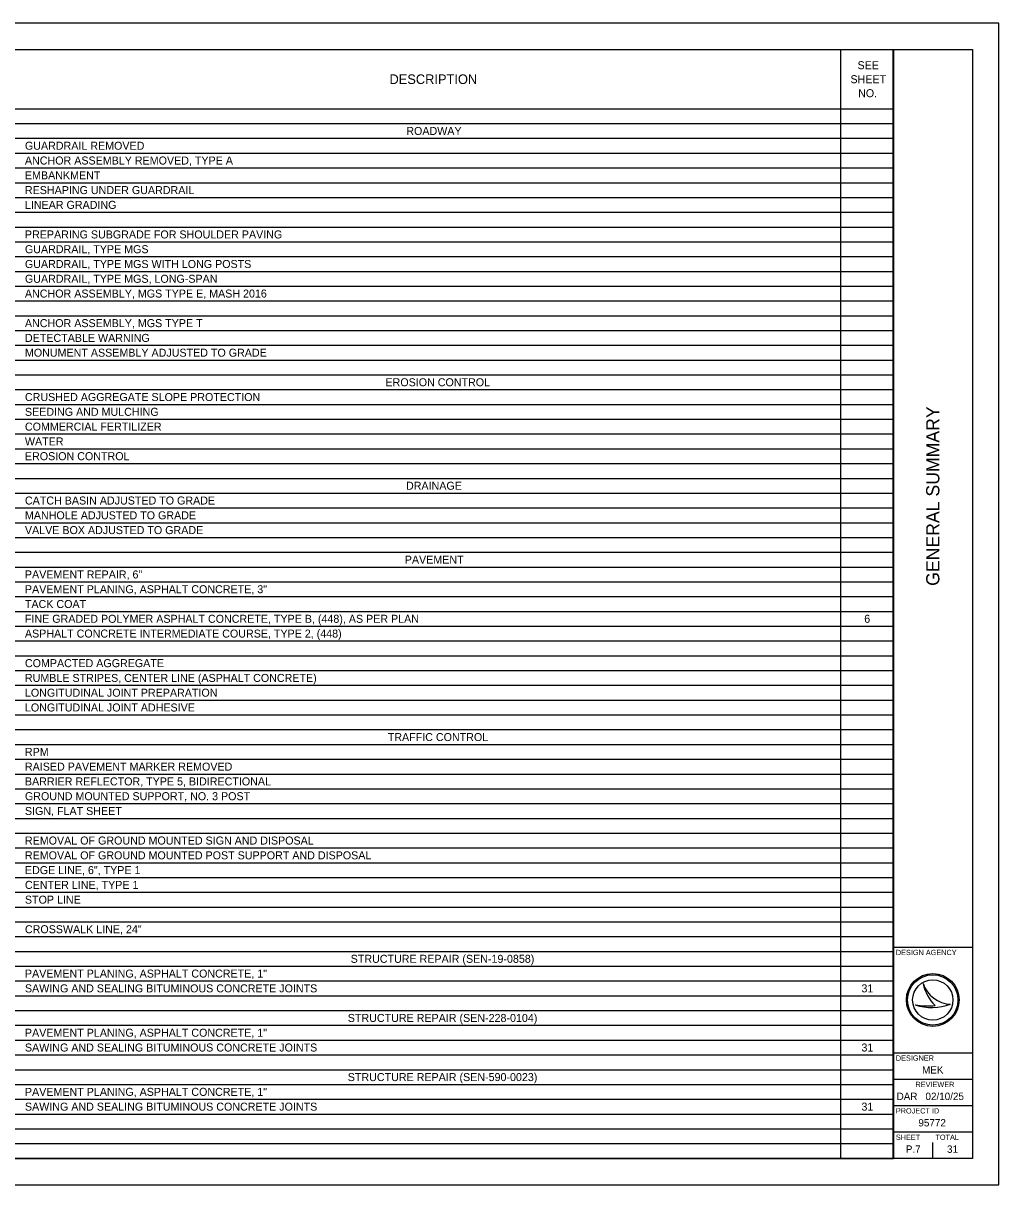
# Model space of a CAD drawing. Extents: x 0 to 34, y 0 to 22.
# Drawn here: x 15.52 to 34, y 0 to 22 of the extents above; entities that cross this region are included whole.
import ezdxf

# ---------------------------------------------------------------- set-up
doc = ezdxf.new("R2010")
doc.units = 0
for name, color, linetype in [('Default', 7, 'Continuous'), ('SH_Border', 7, 'Continuous'), ('SH_Cut_Line', 7, 'Continuous'), ('SH_Data', 7, 'Continuous')]:
    doc.layers.add(name, color=color, linetype=linetype)

msp = doc.modelspace()

# ---------------------------------------------------------------- linework, layer by layer
at = {"layer": 'Default'}
for p, q in [((1.5, 21.5), (32.004, 21.5)), ((30.999, 21.5), (30.999, 0.5)), ((32.004, 21.5), (32.004, 0.5)), ((1.5, 20.38), (32.004, 20.38)), ((1.5, 20.1), (32.004, 20.1)), ((1.5, 19.82), (32.004, 19.82)), ((1.5, 19.54), (32.004, 19.54)), ((1.5, 19.26), (32.004, 19.26)), ((1.5, 18.98), (32.004, 18.98)), ((1.5, 18.7), (32.004, 18.7)), ((1.5, 18.42), (32.004, 18.42)), ((1.5, 18.14), (32.004, 18.14)), ((1.5, 17.86), (32.004, 17.86)), ((1.5, 17.58), (32.004, 17.58)), ((1.5, 17.3), (32.004, 17.3)), ((1.5, 17.02), (32.004, 17.02)), ((1.5, 16.74), (32.004, 16.74)), ((1.5, 16.46), (32.004, 16.46)), ((1.5, 16.18), (32.004, 16.18)), ((1.5, 15.9), (32.004, 15.9)), ((1.5, 15.62), (32.004, 15.62)), ((1.5, 15.34), (32.004, 15.34)), ((1.5, 15.06), (32.004, 15.06)), ((1.5, 14.78), (32.004, 14.78)), ((1.5, 14.5), (32.004, 14.5)), ((1.5, 14.22), (32.004, 14.22)), ((1.5, 13.94), (32.004, 13.94)), ((1.5, 13.66), (32.004, 13.66)), ((1.5, 13.38), (32.004, 13.38)), ((1.5, 13.1), (32.004, 13.1)), ((1.5, 12.82), (32.004, 12.82)), ((1.5, 12.54), (32.004, 12.54)), ((1.5, 12.26), (32.004, 12.26)), ((1.5, 11.98), (32.004, 11.98)), ((1.5, 11.7), (32.004, 11.7)), ((1.5, 11.42), (32.004, 11.42)), ((1.5, 11.14), (32.004, 11.14)), ((1.5, 10.86), (32.004, 10.86)), ((1.5, 10.58), (32.004, 10.58)), ((1.5, 10.3), (32.004, 10.3)), ((1.5, 10.02), (32.004, 10.02)), ((1.5, 9.74), (32.004, 9.74)), ((1.5, 9.46), (32.004, 9.46)), ((1.5, 9.18), (32.004, 9.18)), ((1.5, 8.9), (32.004, 8.9)), ((1.5, 8.62), (32.004, 8.62)), ((1.5, 8.34), (32.004, 8.34)), ((1.5, 8.06), (32.004, 8.06)), ((1.5, 7.78), (32.004, 7.78)), ((1.5, 7.5), (32.004, 7.5)), ((1.5, 7.22), (32.004, 7.22)), ((1.5, 6.94), (32.004, 6.94)), ((1.5, 6.66), (32.004, 6.66)), ((1.5, 6.38), (32.004, 6.38)), ((1.5, 6.1), (32.004, 6.1)), ((1.5, 5.82), (32.004, 5.82)), ((1.5, 5.54), (32.004, 5.54)), ((1.5, 5.26), (32.004, 5.26)), ((1.5, 4.98), (32.004, 4.98)), ((1.5, 4.7), (32.004, 4.7)), ((1.5, 4.42), (32.004, 4.42)), ((1.5, 4.14), (32.004, 4.14)), ((1.5, 3.86), (32.004, 3.86)), ((1.5, 3.58), (32.004, 3.58)), ((1.5, 3.3), (32.004, 3.3)), ((1.5, 3.02), (32.004, 3.02)), ((1.5, 2.74), (32.004, 2.74)), ((1.5, 2.46), (32.004, 2.46)), ((1.5, 2.18), (32.004, 2.18)), ((1.5, 1.9), (32.004, 1.9)), ((1.5, 1.62), (32.004, 1.62)), ((1.5, 1.34), (32.004, 1.34)), ((1.5, 1.06), (32.004, 1.06)), ((1.5, 0.78), (32.004, 0.78)), ((1.5, 0.5), (32.004, 0.5))]:
    msp.add_line(p, q, dxfattribs=at)
at = {"layer": 'SH_Border'}
for p, q in [((32, 0.5), (32, 21.5)), ((32, 4.5), (33.5, 4.5)), ((32, 2.5), (33.5, 2.5)), ((32, 2), (33.5, 2)), ((32, 1.5), (33.5, 1.5)), ((32, 1), (33.5, 1))]:
    msp.add_line(p, q, dxfattribs=at)
msp.add_lwpolyline([(1.5, 21.5), (33.5, 21.5), (33.5, 0.5), (1.5, 0.5)], close=True, dxfattribs=at)
at = {"layer": 'SH_Cut_Line'}
msp.add_lwpolyline([(0, 0), (34, 0), (34, 22), (0, 22)], close=True, dxfattribs=at)
at = {"layer": 'SH_Data'}
for p, q in [((32.567, 3.81), (32.567, 3.81)), ((32.417, 3.41), (32.417, 3.41)), ((32.75, 3.5), (32.75, 3.5)), ((33.087, 3.419), (33.087, 3.419)), ((32.375, 0.675), (32.375, 0.675)), ((32.75, 0.5), (32.75, 0.8))]:
    msp.add_line(p, q, dxfattribs=at)
for radius in [0.5, 0.477, 0.477, 0.382]:
    msp.add_circle((32.75, 3.5), radius, dxfattribs=at)
for centre, radius, start, end in [((33.116, 3.998), 0.58, 198.9257, 198.9319), ((33.347, 3.97), 0.796, 191.6379, 191.6421), ((33.116, 3.998), 0.58, 198.9319, 267.1657), ((33.347, 3.97), 0.796, 191.6421, 226.0947), ((32.739, 4.37), 1.013, 251.4576, 290.0832), ((32.648, 4.654), 1.266, 259.4964, 259.4995), ((32.739, 4.37), 1.013, 251.4527, 251.4576), ((32.648, 4.654), 1.266, 259.4995, 276.6672)]:
    msp.add_arc(centre, radius, start, end, dxfattribs=at)

# ---------------------------------------------------------------- texts
at = {"layer": 'Default'}
for s, height, p in [('SEE ', 0.1515, (31.324, 21.129)), ('DESCRIPTION', 0.18184, (22.456, 20.849)), ('SHEET ', 0.1515, (31.19, 20.864)), ('NO.', 0.1515, (31.335, 20.599)), ('ROADWAY', 0.1515, (22.775, 19.884)), ('GUARDRAIL REMOVED', 0.15153, (15.549, 19.604)), ('ANCHOR ASSEMBLY REMOVED, TYPE A', 0.15153, (15.549, 19.324)), ('EMBANKMENT', 0.1515, (15.549, 19.044)), ('RESHAPING UNDER GUARDRAIL', 0.15153, (15.549, 18.764)), ('LINEAR GRADING', 0.15153, (15.549, 18.484)), ('PREPARING SUBGRADE FOR SHOULDER PAVING', 0.15153, (15.549, 17.924)), ('GUARDRAIL, TYPE MGS', 0.15153, (15.549, 17.644)), ('GUARDRAIL, TYPE MGS WITH LONG POSTS', 0.15153, (15.549, 17.364)), ('GUARDRAIL, TYPE MGS, LONG-SPAN', 0.15153, (15.549, 17.084)), ('ANCHOR ASSEMBLY, MGS TYPE E, MASH 2016', 0.15153, (15.549, 16.804)), ('ANCHOR ASSEMBLY, MGS TYPE T', 0.15153, (15.549, 16.244)), ('DETECTABLE WARNING', 0.15153, (15.549, 15.964)), ('MONUMENT ASSEMBLY ADJUSTED TO GRADE', 0.15153, (15.549, 15.684)), ('EROSION CONTROL', 0.15153, (22.38, 15.124)), ('CRUSHED AGGREGATE SLOPE PROTECTION', 0.15153, (15.549, 14.844)), ('SEEDING AND MULCHING', 0.15153, (15.549, 14.564)), ('COMMERCIAL FERTILIZER', 0.15153, (15.549, 14.284)), ('WATER', 0.1515, (15.549, 14.004)), ('EROSION CONTROL', 0.15153, (15.549, 13.724)), ('DRAINAGE', 0.1515, (22.769, 13.164)), ('CATCH BASIN ADJUSTED TO GRADE', 0.15153, (15.549, 12.884)), ('MANHOLE ADJUSTED TO GRADE', 0.15153, (15.549, 12.604)), ('VALVE BOX ADJUSTED TO GRADE', 0.15153, (15.549, 12.324)), ('PAVEMENT', 0.1515, (22.746, 11.764)), ('PAVEMENT REPAIR, 6"', 0.15153, (15.549, 11.484)), ('PAVEMENT PLANING, ASPHALT CONCRETE, 3"', 0.15153, (15.549, 11.204)), ('TACK COAT', 0.1515, (15.549, 10.924)), ('FINE GRADED POLYMER ASPHALT CONCRETE, TYPE B, (448), AS PER PLAN', 0.15153, (15.549, 10.644)), ('6', 0.152, (31.451, 10.644)), ('ASPHALT CONCRETE INTERMEDIATE COURSE, TYPE 2, (448)', 0.15153, (15.549, 10.364)), ('COMPACTED AGGREGATE', 0.15153, (15.549, 9.804)), ('RUMBLE STRIPES, CENTER LINE (ASPHALT CONCRETE)', 0.15153, (15.549, 9.524)), ('LONGITUDINAL JOINT PREPARATION', 0.15153, (15.549, 9.244)), ('LONGITUDINAL JOINT ADHESIVE', 0.15153, (15.549, 8.964)), ('TRAFFIC CONTROL', 0.15153, (22.424, 8.404)), ('RPM', 0.1515, (15.549, 8.124)), ('RAISED PAVEMENT MARKER REMOVED', 0.15153, (15.549, 7.844)), ('BARRIER REFLECTOR, TYPE 5, BIDIRECTIONAL', 0.15153, (15.549, 7.564)), ('GROUND MOUNTED SUPPORT, NO. 3 POST', 0.15153, (15.549, 7.284)), ('SIGN, FLAT SHEET', 0.15153, (15.549, 7.004)), ('REMOVAL OF GROUND MOUNTED SIGN AND DISPOSAL', 0.15153, (15.549, 6.444)), ('REMOVAL OF GROUND MOUNTED POST SUPPORT AND DISPOSAL', 0.15153, (15.549, 6.164)), ('EDGE LINE, 6", TYPE 1', 0.15153, (15.549, 5.884)), ('CENTER LINE, TYPE 1', 0.15153, (15.549, 5.604)), ('STOP LINE', 0.1515, (15.549, 5.324)), ('CROSSWALK LINE, 24"', 0.15153, (15.549, 4.764)), ('STRUCTURE REPAIR (SEN-19-0858)', 0.15153, (21.721, 4.204)), ('PAVEMENT PLANING, ASPHALT CONCRETE, 1"', 0.15153, (15.549, 3.924)), ('SAWING AND SEALING BITUMINOUS CONCRETE JOINTS', 0.15153, (15.549, 3.644)), ('31', 0.1515, (31.398, 3.644)), ('STRUCTURE REPAIR (SEN-228-0104)', 0.15153, (21.666, 3.084)), ('PAVEMENT PLANING, ASPHALT CONCRETE, 1"', 0.15153, (15.549, 2.804)), ('SAWING AND SEALING BITUMINOUS CONCRETE JOINTS', 0.15153, (15.549, 2.524)), ('31', 0.1515, (31.398, 2.524)), ('STRUCTURE REPAIR (SEN-590-0023)', 0.15153, (21.666, 1.964)), ('PAVEMENT PLANING, ASPHALT CONCRETE, 1"', 0.15153, (15.549, 1.684)), ('SAWING AND SEALING BITUMINOUS CONCRETE JOINTS', 0.15153, (15.549, 1.404)), ('31', 0.1515, (31.398, 1.404))]:
    msp.add_text(s, height=height, dxfattribs=at).set_placement(p)
at = {"layer": 'SH_Data'}
msp.add_text('GENERAL SUMMARY', height=0.25, rotation=90, dxfattribs=at).set_placement((32.875, 11.344))
for s, height, p in [('DESIGN AGENCY', 0.1, (32.05, 4.35)), ('DESIGNER', 0.1, (32.05, 2.35)), ('MEK', 0.14, (32.547, 2.105)), ('REVIEWER', 0.1, (32.422, 1.85)), ('DAR', 0.14, (32.064, 1.605)), ('02/10/25', 0.14, (32.611, 1.605)), ('PROJECT ID', 0.1, (32.05, 1.35)), ('95772', 0.14, (32.477, 1.105)), ('SHEET', 0.1, (32.05, 0.85)), ('TOTAL', 0.1, (32.8, 0.85)), ('P.7', 0.14, (32.239, 0.605)), ('31', 0.14, (33.019, 0.605))]:
    msp.add_text(s, height=height, dxfattribs=at).set_placement(p)

doc.saveas('drawing.dxf')
